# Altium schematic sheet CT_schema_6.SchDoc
size 278 x 170 mm
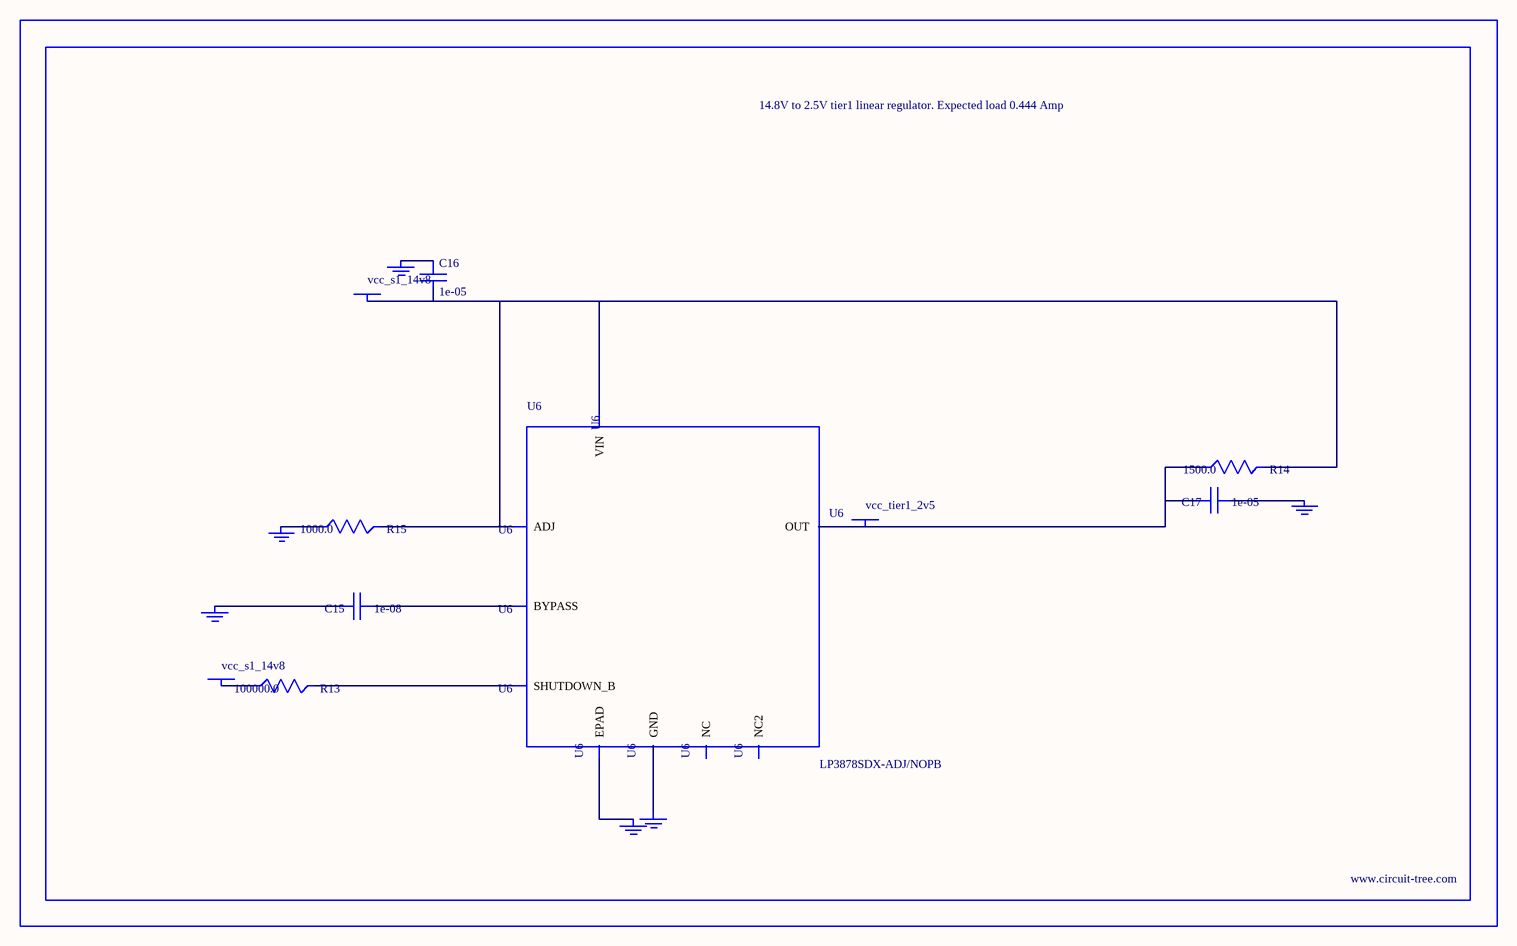
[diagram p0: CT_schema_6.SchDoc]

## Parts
BORDER5  (no value)
C15  1e-08  [C0402]
C16  1e-05  [C1210]
C17  1e-05  [C1210]
GND_INSTANCE_5_0  (no value)
GND_INSTANCE_5_1  (no value)
GND_INSTANCE_5_2  (no value)
GND_INSTANCE_5_3  (no value)
GND_INSTANCE_5_4  (no value)
GND_INSTANCE_5_5  (no value)
POWER_INSTANCE_5_0  vcc_s1_14v8
POWER_INSTANCE_5_1  vcc_s1_14v8
POWER_INSTANCE_5_2  vcc_tier1_2v5
R13  100000.0  [R0603]
R14  1500.0  [R0603]
R15  1000.0  [R0603]
U6  LP3878SDX-ADJ/NOPB  [WSON-8]

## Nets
NetC15_1: C15.1 U6.1(BYPASS)
NetC15_2: C15.2 GND_INSTANCE_5_0.0(GND)
NetC16_1: C16.1 GND_INSTANCE_5_1.0(GND)
NetC16_2: C16.2 POWER_INSTANCE_5_0.0(PWR) R14.2 R15.2 U6.4(VIN) U6.6(ADJ)
NetC17_1: C17.1 GND_INSTANCE_5_2.0(GND)
NetC17_2: C17.2 POWER_INSTANCE_5_2.0(PWR) R14.1 U6.5(OUT)
NetGND_INSTANCE_5_3_0: GND_INSTANCE_5_3.0(GND) R15.1
NetGND_INSTANCE_5_4_0: GND_INSTANCE_5_4.0(GND) U6.PAD(EPAD)
NetGND_INSTANCE_5_5_0: GND_INSTANCE_5_5.0(GND) U6.3(GND)
NetPOWER_INSTANCE_5_1_0: POWER_INSTANCE_5_1.0(PWR) R13.1
NetR13_2: R13.2 U6.8(SHUTDOWN_B)

Not connected (* = marked no-connect by the designer): U6 2(NC) 7(NC2)

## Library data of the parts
BORDER5 = BORDER_PAGE5
C15 = C0402C103K3RAC
C16 = C1210C106K5PACTU
C17 = GRM32DR61E106MA12L
GND_INSTANCE_5_0-GND_INSTANCE_5_5 = GND
POWER_INSTANCE_5_0-POWER_INSTANCE_5_2 = PWR
R13 = RC0603JR-07100KL
R14 = RC0603JR-071K5L
R15 = RC0603JR-071KL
